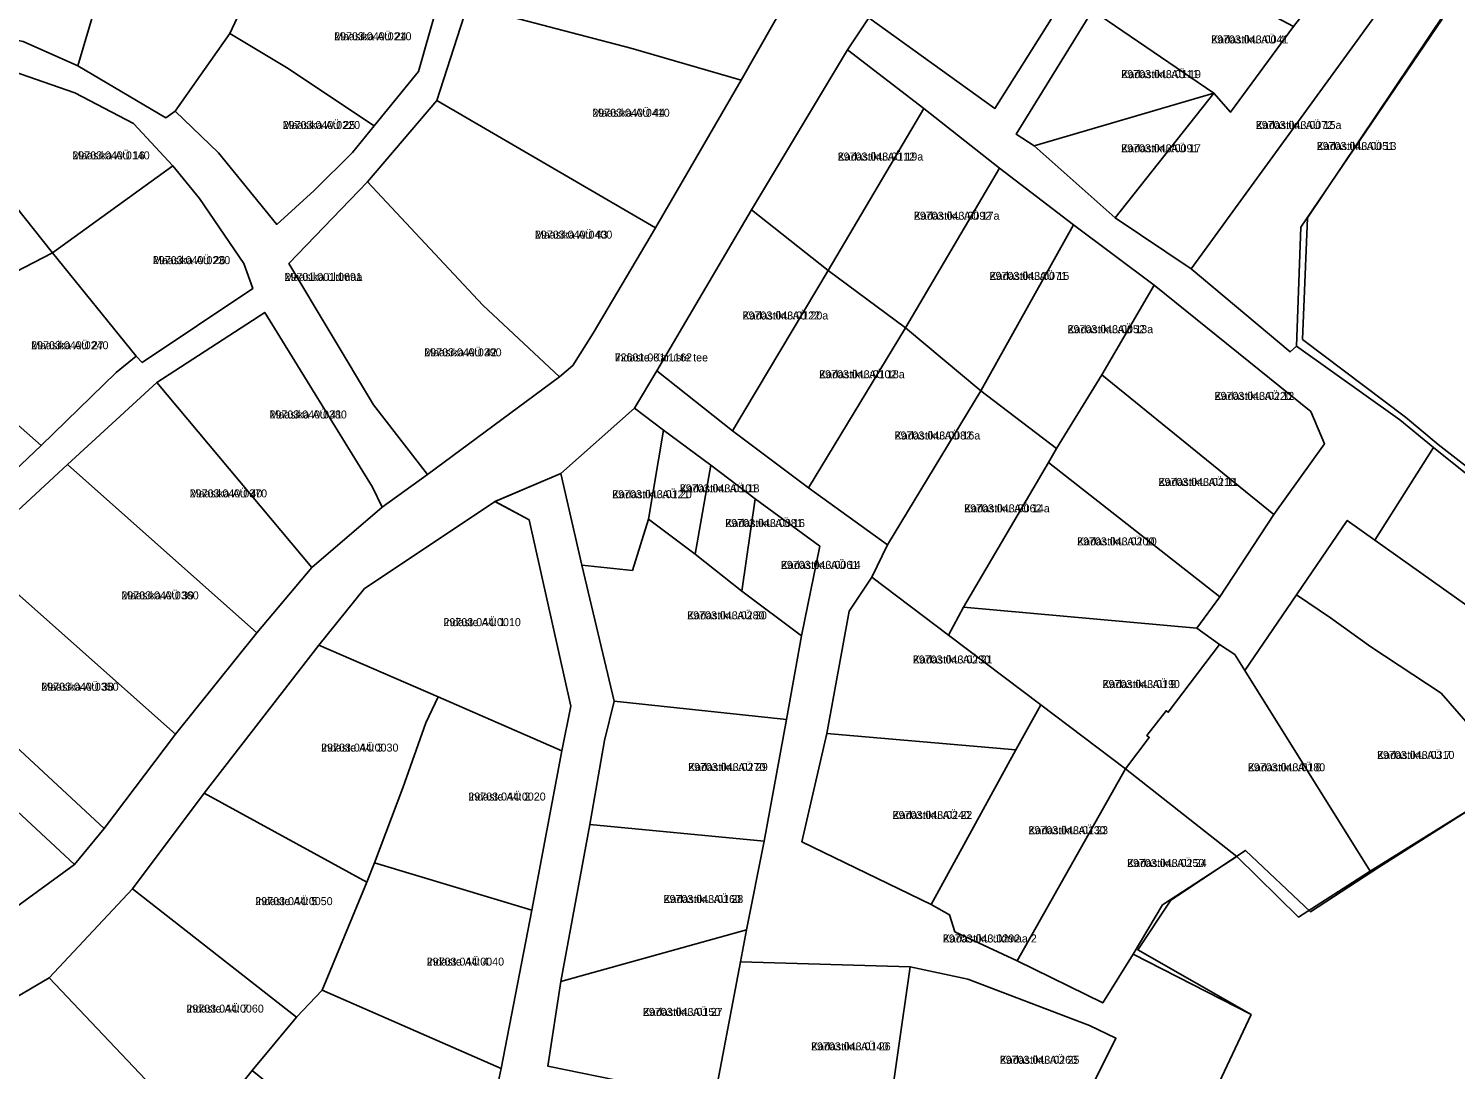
# Model space of a CAD drawing. Extents: x 504287 to 537970, y 6539941 to 6586214.
# Drawn here: x 519484 to 519751.5, y 6560333.9 to 6560529.1 of the extents above; entities that cross this region are included whole.
import ezdxf

# ---------------------------------------------------------------- set-up
doc = ezdxf.new("R2010")
doc.units = 0
for name, color, linetype in [('L_AADRESS', 7, 'Continuous'), ('PIIR', 7, 'Continuous'), ('TUNNUS', 7, 'Continuous')]:
    doc.layers.add(name, color=color, linetype=linetype)

msp = doc.modelspace()

# ---------------------------------------------------------------- linework, layer by layer
at = {"layer": 'PIIR'}
for points in [[(519758.97, 6560668.59), (519733.89, 6560640.72), (519710.13, 6560614.32), (519696.51, 6560602.52), (519676.22, 6560591.64), (519671.78, 6560584.27), (519661.74, 6560566.94), (519651.54, 6560549.59), (519641.52, 6560531.1), (519637.54, 6560525.07), (519619.51, 6560495.06), (519601.79, 6560464.9), (519597.62, 6560457.87), (519583.8, 6560445.64), (519571.46, 6560440.43), (519547, 6560424.1), (519538.39, 6560413.48), (519516.93, 6560385.7), (519503.46, 6560367.79), (519487.87, 6560351.07), (519467.89, 6560339.35)], [(519476.35, 6560360.51), (519492.61, 6560372.35), (519498.16, 6560379.12), (519511.54, 6560396.76), (519526.77, 6560415.79), (519537.12, 6560428.03), (519550.29, 6560439.35), (519558.78, 6560445.49), (519583.53, 6560463.78), (519586.02, 6560465.87), (519589.85, 6560471.99), (519601.54, 6560491.69), (519617.6, 6560519.39), (519629.31, 6560540.07), (519637.86, 6560554.23), (519653.23, 6560579.69), (519656.53, 6560585.5), (519671.23, 6560611.54), (519674.93, 6560618.79), (519681.89, 6560616.88), (519690.16, 6560614.62), (519700.04, 6560622.46), (519722.23, 6560648.11), (519729.98, 6560656.58)], [(519482.99, 6560526.65), (519493.26, 6560522.11), (519509.75, 6560512.35), (519511.51, 6560513.6), (519519.61, 6560505.79), (519530.53, 6560492.35), (519537.53, 6560498.72), (519544.75, 6560505.81), (519548.79, 6560510.86), (519557.09, 6560521.02), (519560.97, 6560534.7), (519560.92, 6560535.88), (519559.1, 6560558.72), (519558.59, 6560560.98), (519555.39, 6560562.91), (519534.7, 6560568.1), (519509.49, 6560575.79), (519483.75, 6560583.81)], [(519703.18, 6560322.99), (519713.19, 6560344.19), (519691.96, 6560356.34), (519698.12, 6560365.63), (519712.14, 6560374.97), (519724.32, 6560363.49), (519737.28, 6560371.88), (519762.93, 6560388.21), (519782.49, 6560401.44), (519769.22, 6560411.65), (519785.83, 6560421.92), (519748.28, 6560451.06), (519742.16, 6560456.22), (519722.85, 6560470.8), (519723.75, 6560493.59), (519749.63, 6560532.14), (519760.67, 6560547.92), (519772.35, 6560544.8), (519797.54, 6560537.62), (519829.04, 6560528.69), (519858.47, 6560520.41), (519883.63, 6560513.22), (519926.01, 6560463.67)], [(519566.31, 6560533.39), (519560.51, 6560515.59), (519547.56, 6560500.32), (519532.82, 6560485.04), (519548.66, 6560458.54), (519558.78, 6560445.49), (519550.29, 6560439.35), (519548.45, 6560443.11), (519528.28, 6560475.86), (519508.05, 6560462.74), (519491.3, 6560447.34), (519473.29, 6560430.71)], [(519683.46, 6560532.48), (519669.12, 6560509.28), (519672.52, 6560507.08), (519687.73, 6560493.58), (519701.98, 6560484.01), (519720.49, 6560468.45), (519721.71, 6560469.51), (519741.06, 6560455.7), (519747.37, 6560450.55), (519736.4, 6560433.16), (519731.22, 6560436.86), (519721.72, 6560422.92), (519712.02, 6560408.73), (519710.13, 6560411.73), (519707.25, 6560413.61), (519703.02, 6560416.64), (519707.34, 6560422.52), (519717.48, 6560437.95), (519726.95, 6560451.24), (519724.38, 6560457.3), (519695.03, 6560480.95), (519679.9, 6560492.25), (519666.01, 6560502.93), (519651.86, 6560514.06), (519637.54, 6560525.07), (519641.52, 6560531.1), (519665.15, 6560514.09), (519675.73, 6560530.86)], [(519467.72, 6560433.28), (519486.35, 6560450.87), (519500.45, 6560464.61), (519504.16, 6560467.62), (519505.29, 6560466.48), (519526.07, 6560480.36), (519524.34, 6560485.01), (519516.05, 6560497.24), (519511.04, 6560503.32), (519503.64, 6560511.29), (519492.65, 6560517), (519478.03, 6560522.07)], [(519684.01, 6560332.12), (519687.85, 6560339.76), (519682.91, 6560342.14), (519660.08, 6560350.82), (519649.27, 6560353.16), (519617.48, 6560354.09), (519618.57, 6560360.09), (519621.9, 6560376.73), (519626.06, 6560399.51), (519628.93, 6560415.24), (519632.32, 6560432.04), (519620.23, 6560440.93), (519611.92, 6560447.21), (519603.02, 6560453.8), (519597.62, 6560457.87), (519601.79, 6560464.9), (519615.98, 6560453.67), (519630.23, 6560442.95), (519645.02, 6560432.27), (519642.07, 6560426.22), (519637.83, 6560419.85), (519633.63, 6560396.93), (519628.99, 6560376.62), (519653.2, 6560364.84), (519656.64, 6560362.91), (519657.68, 6560359.73), (519669.32, 6560354.29), (519685.39, 6560346.4), (519691.1, 6560355.54), (519713.19, 6560344.19), (519703.18, 6560322.99)], [(519571.27, 6560327.97), (519572.61, 6560334.11), (519578.36, 6560363.76), (519584, 6560393.63), (519585.65, 6560402.05), (519577.84, 6560436.98), (519571.44, 6560440.4), (519583.8, 6560445.64), (519587.72, 6560428.48), (519593.8, 6560402.99), (519592, 6560395.6), (519589.19, 6560379.86), (519583.8, 6560350.39), (519581.34, 6560334.53), (519597.27, 6560331.27)], [(519480.66, 6560395.36), (519498.16, 6560379.12), (519492.61, 6560372.35), (519460.21, 6560402.41)]]:
    msp.add_lwpolyline(points, dxfattribs=at)
for points in [[(519466.73, 6560529.79), (519475.31, 6560557.55), (519501.54, 6560550.19), (519493.26, 6560522.11), (519482.99, 6560526.65)], [(519564.26, 6560559.32), (519629.31, 6560540.07), (519617.6, 6560519.39), (519596.92, 6560525.41), (519566.31, 6560533.39)], [(519501.54, 6560550.19), (519528.63, 6560542.91), (519521.74, 6560528.12), (519511.51, 6560513.6), (519509.75, 6560512.35), (519493.26, 6560522.11)], [(519651.54, 6560549.59), (519675.73, 6560530.86), (519665.15, 6560514.09), (519641.52, 6560531.1)], [(519521.74, 6560528.12), (519528.63, 6560542.91), (519534.41, 6560541.68), (519560.92, 6560535.88), (519560.97, 6560534.7), (519557.09, 6560521.02), (519548.79, 6560510.86), (519532.38, 6560521.8)], [(519706.2, 6560516.97), (519709.33, 6560513.37), (519721.17, 6560529.45), (519727.5, 6560537.65), (519732.08, 6560543.74), (519740.41, 6560536.98), (519701.98, 6560484.01), (519687.73, 6560493.58)], [(519687.1, 6560538.98), (519688.86, 6560536.86), (519702.86, 6560539.2), (519721.17, 6560529.45), (519709.33, 6560513.37), (519706.2, 6560516.97), (519683.46, 6560532.48)], [(519740.41, 6560536.98), (519749.01, 6560530.86), (519722.54, 6560491.81), (519721.71, 6560469.51), (519720.49, 6560468.45), (519701.98, 6560484.01)], [(519566.31, 6560533.39), (519596.92, 6560525.41), (519617.6, 6560519.39), (519601.54, 6560491.69), (519560.51, 6560515.59)], [(519683.46, 6560532.48), (519706.2, 6560516.97), (519672.52, 6560507.08), (519669.12, 6560509.28)], [(519511.51, 6560513.6), (519521.74, 6560528.12), (519532.38, 6560521.8), (519548.79, 6560510.86), (519544.75, 6560505.81), (519537.53, 6560498.72), (519530.53, 6560492.35), (519519.61, 6560505.79)], [(519466.63, 6560515.45), (519462.49, 6560519.13), (519466.36, 6560523.09), (519473.2, 6560517.28), (519469.29, 6560512.49), (519469.09, 6560511.31), (519488.51, 6560487.03), (519469.1, 6560477.02), (519448.9, 6560496.33)], [(519637.54, 6560525.07), (519651.86, 6560514.06), (519633.93, 6560483.7), (519619.51, 6560495.06)], [(519469.09, 6560511.31), (519469.29, 6560512.49), (519473.2, 6560517.28), (519478.03, 6560522.07), (519492.65, 6560517), (519503.64, 6560511.29), (519511.04, 6560503.32), (519488.51, 6560487.03)], [(519547.56, 6560500.32), (519560.51, 6560515.59), (519601.54, 6560491.69), (519589.85, 6560471.99), (519586.02, 6560465.87), (519583.53, 6560463.78), (519569.16, 6560477.22)], [(519672.52, 6560507.08), (519706.2, 6560516.97), (519687.73, 6560493.58)], [(519651.86, 6560514.06), (519666.01, 6560502.93), (519648.43, 6560472.97), (519633.93, 6560483.7)], [(519504.16, 6560467.62), (519488.51, 6560487.03), (519511.04, 6560503.32), (519516.05, 6560497.24), (519524.34, 6560485.01), (519526.07, 6560480.36), (519505.29, 6560466.48)], [(519666.01, 6560502.93), (519679.9, 6560492.25), (519662.5, 6560461.13), (519648.43, 6560472.97)], [(519532.82, 6560485.04), (519547.56, 6560500.32), (519569.16, 6560477.22), (519583.53, 6560463.78), (519558.78, 6560445.49), (519548.66, 6560458.54)], [(519619.51, 6560495.06), (519633.93, 6560483.7), (519615.98, 6560453.67), (519601.79, 6560464.9)], [(519679.9, 6560492.25), (519695.03, 6560480.95), (519685.18, 6560464.13), (519676.7, 6560450.34), (519662.5, 6560461.13)], [(519469.1, 6560477.02), (519488.51, 6560487.03), (519504.16, 6560467.62), (519500.45, 6560464.61), (519486.35, 6560450.87), (519463.33, 6560471.19)], [(519633.93, 6560483.7), (519648.43, 6560472.97), (519630.23, 6560442.95), (519615.98, 6560453.67)], [(519695.03, 6560480.95), (519724.38, 6560457.3), (519726.95, 6560451.24), (519717.48, 6560437.95), (519685.18, 6560464.13)], [(519528.28, 6560475.86), (519548.45, 6560443.11), (519550.29, 6560439.35), (519537.12, 6560428.03), (519508.05, 6560462.74)], [(519648.43, 6560472.97), (519662.5, 6560461.13), (519645.02, 6560432.27), (519630.23, 6560442.95)], [(519463.33, 6560471.19), (519486.35, 6560450.87), (519467.72, 6560433.28), (519446.85, 6560452.96)], [(519685.18, 6560464.13), (519717.48, 6560437.95), (519707.34, 6560422.52), (519675.22, 6560447.7), (519676.7, 6560450.34)], [(519508.05, 6560462.74), (519537.12, 6560428.03), (519526.77, 6560415.79), (519491.3, 6560447.34)], [(519662.5, 6560461.13), (519676.7, 6560450.34), (519675.22, 6560447.7), (519659.27, 6560420.56), (519656.49, 6560415.36), (519642.07, 6560426.22), (519645.02, 6560432.27)], [(519597.62, 6560457.87), (519603.02, 6560453.8), (519600.24, 6560437.11), (519597.21, 6560427.49), (519587.72, 6560428.48), (519583.8, 6560445.64)], [(519603.02, 6560453.8), (519611.92, 6560447.21), (519608.99, 6560430.5), (519600.24, 6560437.11)], [(519747.37, 6560450.55), (519784.26, 6560420.94), (519768.54, 6560410.35), (519736.4, 6560433.16)], [(519491.3, 6560447.34), (519526.77, 6560415.79), (519511.54, 6560396.76), (519473.29, 6560430.71)], [(519611.92, 6560447.21), (519620.23, 6560440.93), (519617.74, 6560423.56), (519608.99, 6560430.5)], [(519707.34, 6560422.52), (519703.02, 6560416.64), (519659.27, 6560420.56), (519675.22, 6560447.7)], [(519547, 6560424.1), (519571.46, 6560440.43), (519577.84, 6560436.98), (519585.65, 6560402.05), (519584, 6560393.63), (519560.76, 6560403.78), (519538.39, 6560413.48)], [(519620.23, 6560440.93), (519632.32, 6560432.04), (519628.93, 6560415.24), (519617.74, 6560423.56)], [(519600.24, 6560437.11), (519608.99, 6560430.5), (519617.74, 6560423.56), (519628.93, 6560415.24), (519626.06, 6560399.51), (519593.8, 6560402.99), (519587.72, 6560428.48), (519597.21, 6560427.49)], [(519731.22, 6560436.86), (519736.4, 6560433.16), (519768.54, 6560410.35), (519780.84, 6560400.25), (519761.57, 6560387.29), (519753.9, 6560398.64), (519748.82, 6560404.48), (519735.65, 6560413.14), (519728.07, 6560418.57), (519721.72, 6560422.92)], [(519460.06, 6560414.57), (519462.72, 6560420.51), (519473.29, 6560430.71), (519511.54, 6560396.76), (519498.16, 6560379.12), (519480.66, 6560395.36)], [(519642.07, 6560426.22), (519656.49, 6560415.36), (519673.77, 6560402.26), (519669.1, 6560393.84), (519633.63, 6560396.93), (519637.83, 6560419.85)], [(519721.72, 6560422.92), (519728.07, 6560418.57), (519735.65, 6560413.14), (519748.82, 6560404.48), (519753.9, 6560398.64), (519761.57, 6560387.29), (519735.51, 6560371.08), (519712.02, 6560408.73)], [(519659.27, 6560420.56), (519703.02, 6560416.64), (519707.25, 6560413.61), (519697.65, 6560400.88), (519697.26, 6560401.18), (519693.66, 6560396.51), (519694.1, 6560396.18), (519689.65, 6560390.29), (519673.77, 6560402.26), (519656.49, 6560415.36)], [(519516.93, 6560385.7), (519538.39, 6560413.48), (519560.76, 6560403.78), (519558.5, 6560398.93), (519554.16, 6560386.74), (519548.88, 6560372.66), (519547.41, 6560369.05)], [(519707.25, 6560413.61), (519710.13, 6560411.73), (519712.02, 6560408.73), (519735.51, 6560371.08), (519722.08, 6560362.47), (519710.54, 6560373.82), (519689.65, 6560390.29), (519694.1, 6560396.18), (519693.66, 6560396.51), (519697.26, 6560401.18), (519697.65, 6560400.88)], [(519460.21, 6560402.41), (519492.61, 6560372.35), (519476.35, 6560360.51), (519444.36, 6560389.55)], [(519558.5, 6560398.93), (519560.76, 6560403.78), (519584, 6560393.63), (519578.36, 6560363.76), (519548.88, 6560372.66), (519554.16, 6560386.74)], [(519593.8, 6560402.99), (519626.06, 6560399.51), (519621.9, 6560376.73), (519589.19, 6560379.86), (519592, 6560395.6)], [(519673.77, 6560402.26), (519689.65, 6560390.29), (519669.32, 6560354.29), (519657.68, 6560359.73), (519656.64, 6560362.91), (519653.2, 6560364.84), (519669.1, 6560393.84)], [(519633.63, 6560396.93), (519669.1, 6560393.84), (519653.2, 6560364.84), (519628.99, 6560376.62)], [(519689.65, 6560390.29), (519710.54, 6560373.82), (519696.57, 6560364.75), (519691.1, 6560355.54), (519685.39, 6560346.4), (519669.32, 6560354.29)], [(519503.46, 6560367.79), (519516.93, 6560385.7), (519547.41, 6560369.05), (519539.02, 6560348.76), (519534.22, 6560343.74)], [(519589.19, 6560379.86), (519621.9, 6560376.73), (519618.57, 6560360.09), (519583.8, 6560350.39)], [(519547.41, 6560369.05), (519548.88, 6560372.66), (519578.36, 6560363.76), (519572.61, 6560334.11), (519539.02, 6560348.76)], [(519487.87, 6560351.07), (519503.46, 6560367.79), (519534.22, 6560343.74), (519525.91, 6560333.71), (519516.04, 6560321.35)], [(519583.8, 6560350.39), (519618.57, 6560360.09), (519617.48, 6560354.09), (519612.47, 6560327.8), (519597.27, 6560331.27), (519581.34, 6560334.53)], [(519617.48, 6560354.09), (519649.27, 6560353.16), (519644.68, 6560320.89), (519612.47, 6560327.8)], [(519649.27, 6560353.16), (519660.08, 6560350.82), (519682.91, 6560342.14), (519687.85, 6560339.76), (519684.01, 6560332.12), (519676.08, 6560316.78), (519644.68, 6560320.89)], [(519467.89, 6560339.35), (519487.87, 6560351.07), (519516.04, 6560321.35), (519509.44, 6560314.9), (519499.42, 6560306.41)], [(519534.22, 6560343.74), (519539.02, 6560348.76), (519572.61, 6560334.11), (519571.27, 6560327.97), (519554.91, 6560310.21), (519525.91, 6560333.71)]]:
    msp.add_lwpolyline(points, close=True, dxfattribs=at)

# ---------------------------------------------------------------- texts
at = {"layer": 'L_AADRESS'}
for s, p in [('Maasika AÜ 24', (519541.29, 6560526.88)), ('Kadastiku AÜ 4', (519705.69, 6560526.29)), ('Kadastiku AÜ 19', (519688.85, 6560519.78)), ('Maasika AÜ 25', (519531.64, 6560510.24)), ('Maasika AÜ 44', (519589.69, 6560512.54)), ('Kadastiku AÜ 15a', (519714.07, 6560510.24)), ('Kadastiku AÜ 17', (519688.82, 6560505.88)), ('Kadastiku AÜ 13', (519725.49, 6560506.3)), ('Maasika AÜ 16', (519492.2, 6560504.55)), ('Kadastiku AÜ 19a', (519635.68, 6560504.33)), ('Kadastiku AÜ 17a', (519649.97, 6560493.23)), ('Maasika AÜ 43', (519578.93, 6560489.69)), ('Maasika AÜ 26', (519507.3, 6560484.9)), ('Maasika üldmaa', (519531.98, 6560481.76)), ('Kadastiku AÜ 15', (519664.16, 6560481.95)), ('Kadastiku AÜ 20a', (519617.86, 6560474.53)), ('Kadastiku AÜ 13a', (519678.77, 6560471.96)), ('Maasika AÜ 27', (519484.48, 6560468.95)), ('Maasika AÜ 42', (519558.18, 6560467.62)), ('Indaste-Karuste tee', (519593.87, 6560466.66)), ('Kadastiku AÜ 18a', (519632.2, 6560463.51)), ('Kadastiku AÜ 12', (519706.33, 6560459.45)), ('Maasika AÜ 41', (519529.17, 6560455.97)), ('Kadastiku AÜ 16a', (519646.36, 6560452.03)), ('Kadastiku AÜ 11', (519695.82, 6560443.32)), ('Maasika AÜ 40', (519514.21, 6560441.17)), ('Kadastiku AÜ 20', (519593.41, 6560441.02)), ('Kadastiku AÜ 18', (519606.08, 6560442.12)), ('Kadastiku AÜ 14a', (519659.39, 6560438.37)), ('Kadastiku AÜ 16', (519614.61, 6560435.61)), ('Kadastiku AÜ 10', (519680.56, 6560432.17)), ('Kadastiku AÜ 14', (519625.03, 6560427.77)), ('Maasika AÜ 39', (519501.39, 6560422.05)), ('Indaste AÜ 1', (519561.78, 6560417.03)), ('Kadastiku AÜ 30', (519607.47, 6560418.31)), ('Kadastiku AÜ 21', (519649.78, 6560410.03)), ('Maasika AÜ 38', (519486.38, 6560404.92)), ('Kadastiku AÜ 9', (519685.34, 6560405.42)), ('Indaste AÜ 3', (519538.84, 6560393.51)), ('Kadastiku AÜ 29', (519607.64, 6560389.86)), ('Kadastiku AÜ 8', (519712.58, 6560389.82)), ('Kadastiku AÜ 7', (519736.8, 6560392.13)), ('Indaste AÜ 2', (519566.44, 6560384.33)), ('Kadastiku AÜ 22', (519645.98, 6560380.88)), ('Kadastiku AÜ 23', (519671.43, 6560378.02)), ('Kadastiku AÜ 24', (519689.93, 6560371.87)), ('Indaste AÜ 5', (519526.5, 6560364.72)), ('Kadastiku AÜ 28', (519603.04, 6560365.12)), ('Kadastiku üldmaa 2', (519655.4, 6560357.72)), ('Indaste AÜ 4', (519558.64, 6560353.38)), ('Indaste AÜ 7', (519513.59, 6560344.57)), ('Kadastiku AÜ 27', (519599.17, 6560343.95)), ('Kadastiku AÜ 26', (519630.68, 6560337.49)), ('Kadastiku AÜ 25', (519666.06, 6560334.97))]:
    msp.add_text(s, height=1.5, dxfattribs=at).set_placement(p)
at = {"layer": 'TUNNUS'}
for s, p in [('29703:040:0210', (519541.29, 6560526.88)), ('29703:043:0041', (519705.69, 6560526.29)), ('29703:043:0111', (519688.85, 6560519.78)), ('29703:040:0410', (519589.69, 6560512.54)), ('29703:040:0220', (519531.64, 6560510.24)), ('29703:043:0072', (519714.07, 6560510.24)), ('29703:043:0091', (519688.82, 6560505.88)), ('29703:043:0051', (519725.49, 6560506.3)), ('29703:040:0140', (519492.2, 6560504.55)), ('29703:043:0112', (519635.68, 6560504.33)), ('29703:043:0092', (519649.97, 6560493.23)), ('29703:040:0400', (519578.93, 6560489.69)), ('29703:040:0230', (519507.3, 6560484.9)), ('29701:001:0691', (519531.98, 6560481.76)), ('29703:043:0071', (519664.16, 6560481.95)), ('29703:043:0122', (519617.86, 6560474.53)), ('29703:043:0052', (519678.77, 6560471.96)), ('29703:040:0240', (519484.48, 6560468.95)), ('29703:040:0390', (519558.18, 6560467.62)), ('72601:001:1162', (519593.87, 6560466.66)), ('29703:043:0102', (519632.2, 6560463.51)), ('29703:043:0220', (519706.33, 6560459.45)), ('29703:040:0380', (519529.17, 6560455.97)), ('29703:043:0082', (519646.36, 6560452.03)), ('29703:040:0370', (519514.21, 6560441.17)), ('29703:043:0121', (519593.41, 6560441.02)), ('29703:043:0101', (519606.08, 6560442.12)), ('29703:043:0210', (519695.82, 6560443.32)), ('29703:043:0062', (519659.39, 6560438.37)), ('29703:043:0081', (519614.61, 6560435.61)), ('29703:043:0200', (519680.56, 6560432.17)), ('29703:043:0061', (519625.03, 6560427.77)), ('29703:040:0360', (519501.39, 6560422.05)), ('29703:044:0010', (519561.78, 6560417.03)), ('29703:043:0280', (519607.47, 6560418.31)), ('29703:043:0230', (519649.78, 6560410.03)), ('29703:040:0350', (519486.38, 6560404.92)), ('29703:043:0190', (519685.34, 6560405.42)), ('29703:044:0030', (519538.84, 6560393.51)), ('29703:043:0310', (519736.8, 6560392.13)), ('29703:043:0270', (519607.64, 6560389.86)), ('29703:043:0180', (519712.58, 6560389.82)), ('29703:044:0020', (519566.44, 6560384.33)), ('29703:043:0240', (519645.98, 6560380.88)), ('29703:043:0130', (519671.43, 6560378.02)), ('29703:043:0250', (519689.93, 6560371.87)), ('29703:044:0050', (519526.5, 6560364.72)), ('29703:043:0160', (519603.04, 6560365.12)), ('29703:043:0292', (519655.4, 6560357.72)), ('29703:044:0040', (519558.64, 6560353.38)), ('29703:044:0060', (519513.59, 6560344.57)), ('29703:043:0150', (519599.17, 6560343.95)), ('29703:043:0140', (519630.68, 6560337.49)), ('29703:043:0260', (519666.06, 6560334.97))]:
    msp.add_text(s, height=1.5, dxfattribs=at).set_placement(p)

doc.saveas('drawing.dxf')
